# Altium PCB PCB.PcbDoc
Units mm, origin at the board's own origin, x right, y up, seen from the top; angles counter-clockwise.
Board outline 60.71 x 19.3 mm, 2 copper layers (Top Layer, Bottom Layer); 4 components, 4 nets, 31 pads, 2 vias.
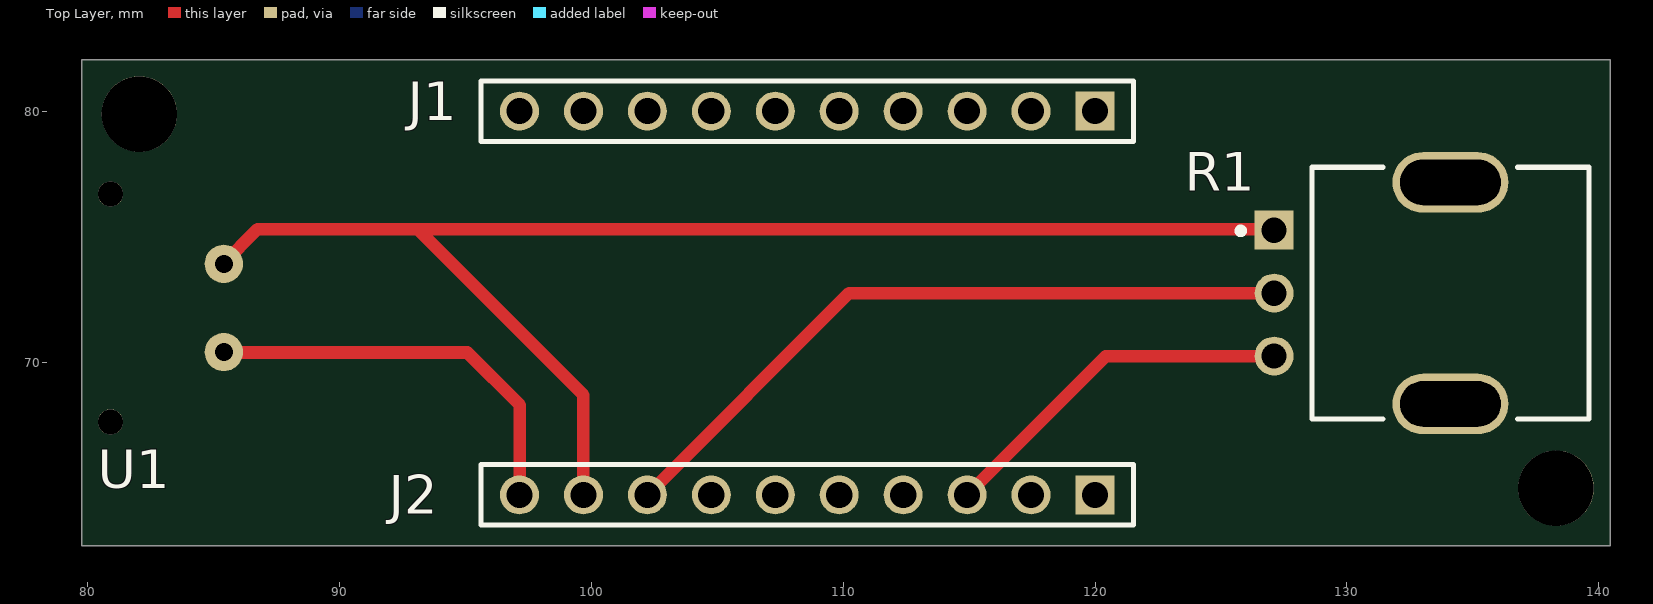
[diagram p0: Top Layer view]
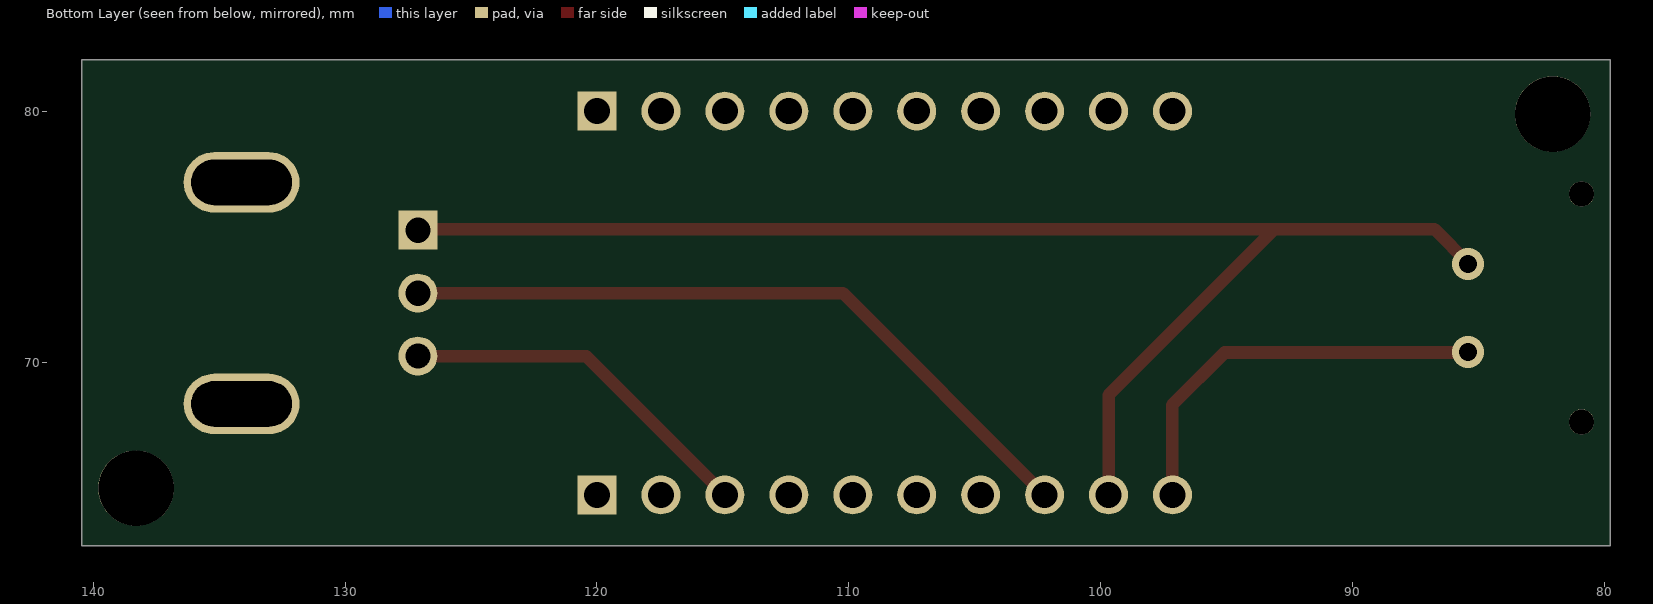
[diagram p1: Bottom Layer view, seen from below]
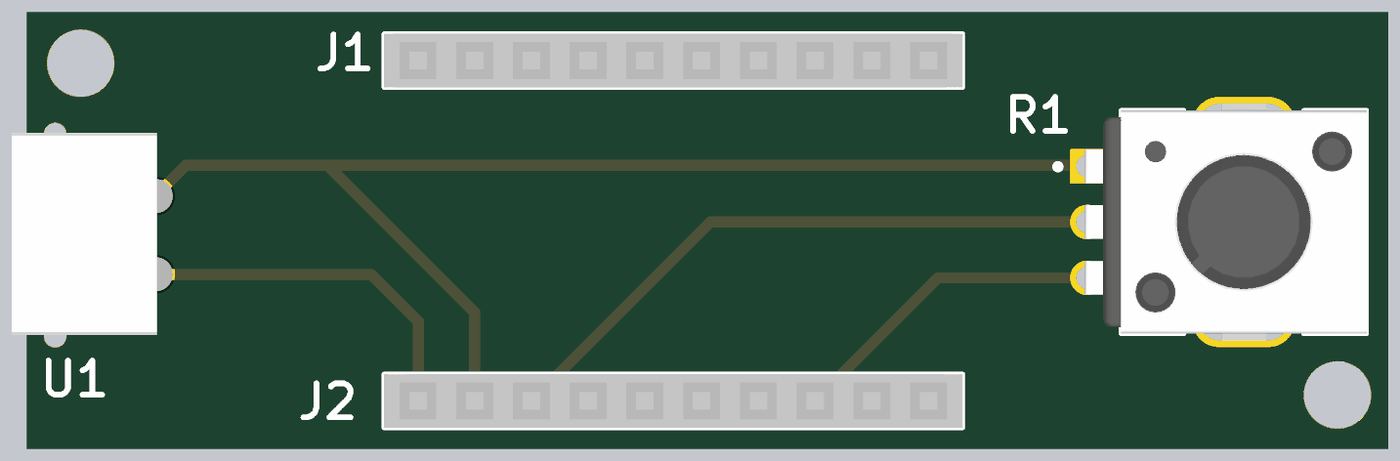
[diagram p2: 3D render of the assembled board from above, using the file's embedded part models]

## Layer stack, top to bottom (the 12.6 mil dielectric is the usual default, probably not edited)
Top Solder: solder mask 0.0102, Solder Resist, Dk 3.5
Top Layer: signal copper 0.0356
Dielectric 1: dielectric 0.32, FR-4, Dk 4.8
Bottom Layer: signal copper 0.0356
Bottom Solder: solder mask 0.0102, Solder Resist, Dk 3.5

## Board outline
79.756,62.738 140.462,62.738 140.462,82.042 79.756,82.042

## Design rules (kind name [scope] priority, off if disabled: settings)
Clearance [All] p1: gap=0.254 ignorepadtopadclearanceinfootprint=FALSE
PolygonConnect [All] p1: connectstyle=Relief reliefconductorwidth=0.254 reliefentries=4 polygonreliefangle="90 Angle" airgapwidth=0.254
RoutingVias [All] p1: holewidth=0.711 width=1.27 viastyle="Through Hole" minholewidth=0.711 minwidth=1.27 maxholewidth=0.711 maxwidth=1.27
SolderMaskExpansion [All] p1: expansion=0.102 istentingtop=FALSE
SupplyNets "Schematic Supply Nets_2" [InNet('+5')] p1: voltage=0.000
SupplyNets "Schematic Supply Nets_1" [InNet('+3v3')] p2: voltage=0.000
SupplyNets "Schematic Supply Nets" [InNet('GND')] p3: voltage=0.000
Width [All] p1: maxlimit=0.5 minlimit=0.254 preferedwidth=0.254
30 further rules are at their usual default settings.

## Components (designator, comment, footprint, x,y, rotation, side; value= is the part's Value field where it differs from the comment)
J1 "SSW-110-03-G-S" SMTC-SSW-110-03-X-S 120,80 r180 top locked
J2 "SSW-110-03-G-S" SMTC-SSW-110-03-X-S 120,64.76 r180 top locked
R1 "PTV09A-4225F-B102" FP-PTV09A-4-MFG 134.112,72.771 r270 top
U1 "USB Type C 2 Pin Connector" "USB C Power Connector" 78.899,67.658 r0 top

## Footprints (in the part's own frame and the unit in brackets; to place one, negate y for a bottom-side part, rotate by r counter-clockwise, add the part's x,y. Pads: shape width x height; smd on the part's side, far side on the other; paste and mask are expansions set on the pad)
FP-PTV09A-4-MFG [mm]
  rect 1.55x1.55 hole 1 paste-2539.97 mask+0: 1(-2.5,-7)
  round 1.55 hole 1 paste-2539.97 mask+0: 2(0,-7) 3(2.5,-7)
  rrect100% 2.4x4.6 hole 4 slot 1.8 at 0 deg paste-2539.97 mask+0: 4(-4.4,0) 5(4.4,0)
  silkscreen extent -5,-8.45 5,5.5, body extent -5.8,-7.88 5.8,5.6, height 0.25
SMTC-SSW-110-03-X-S [mm] "SQ Post Socket, 1x10 Pins, Vertical, 2.54mm Pitch, Female"
  rect 1.55x1.55 hole 1.04: 1(0,0)
  round 1.55 hole 1.04: 2(2.54,0) 3(5.08,0) 4(7.62,0) 5(10.16,0) 6(12.7,0) 7(15.24,0) 8(17.78,0) 9(20.32,0) 10(22.86,0)
  silkscreen extent -1.53,-1.2 24.39,1.2, body extent -1.52,-1.21 24.38,1.21, height 8.51
"USB C Power Connector" [mm]
  round 1.524 smd: GND(6.5,6.275) VCC(6.5,2.775)
  round 1 hole 1 mask+0: NC(2,0)
  round 1 hole 1 paste-2539.97 mask+0: NC(2,9.05)
  body extent 0.05,0.05 6.55,9.1, height 3

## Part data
J1 J2: library part CMP-1023-00394-1, "SQ Post Socket, Through-hole, Vertical, -55 to 125 degC, 2.54 mm Pitch, 10-Pin, Female, RoHS", Manufacturer=Samtec, Temperature Range="-55 to 125 degC"
R1: library part CMP-07234-000055-1, "POT 1K OHM 1/20W CARBON LINEAR", Max Operating Temperature=50°C, Max Power Dissipation=50mW, Min Operating Temperature=-10°C, Package Quantity=100, Resistance=1kR, Resistance Tolerance=20%, Resistor Type=Carbon

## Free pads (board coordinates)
  round 3 hole 3 paste-2539.97 mask+0: 12(82.042,79.883) 12(138.303,65.024)

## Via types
v1: diameter 1.27, hole 0.711, Top Layer to Bottom Layer, 2 vias

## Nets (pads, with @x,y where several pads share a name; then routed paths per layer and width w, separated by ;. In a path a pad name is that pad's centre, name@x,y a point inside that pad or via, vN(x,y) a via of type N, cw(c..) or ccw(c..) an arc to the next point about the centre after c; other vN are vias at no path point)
+3v3: J2.8 R1.2 | length 28.2
  Top Layer w0.5: J2.8 110.231,72.771 R1.2
+5: J2.10 U1.VCC | length 16.2
  Top Layer w0.5: U1.VCC@85.344,70.414 95.067,70.414 97.155,68.326 97.155,64.775 J2.10
  other v1: 85.399,70.433
DATA: J2.3 R1.3 | length 14.5
  Top Layer w0.5: J2.3 120.431,70.271 R1.3
GND: J2.9 R1.1 U1.GND | length 55.6
  Top Layer w0.5: U1.GND@85.344,73.914 86.741,75.311 93.091,75.311 ; J2.9 99.68,68.722 93.091,75.311 ; R1.1 127.072,75.311 93.091,75.311
  other v1: 85.399,73.933
pads on no net: J1.1 J1.2 J1.3 J1.4 J1.5 J1.6 J1.7 J1.8 J1.9 J1.10 J2.1 J2.2 J2.4 J2.5 J2.6 J2.7 R1.4 R1.5 U1.NC

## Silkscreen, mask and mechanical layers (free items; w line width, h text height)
PCBBorder:
  the board outline again, w0.254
